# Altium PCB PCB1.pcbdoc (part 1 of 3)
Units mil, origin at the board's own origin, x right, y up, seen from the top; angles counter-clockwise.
Board outline 4706 x 2788 mil, 2 copper layers (Top Layer, Bottom Layer); 153 components, 206 nets, 1095 pads, 513 vias.
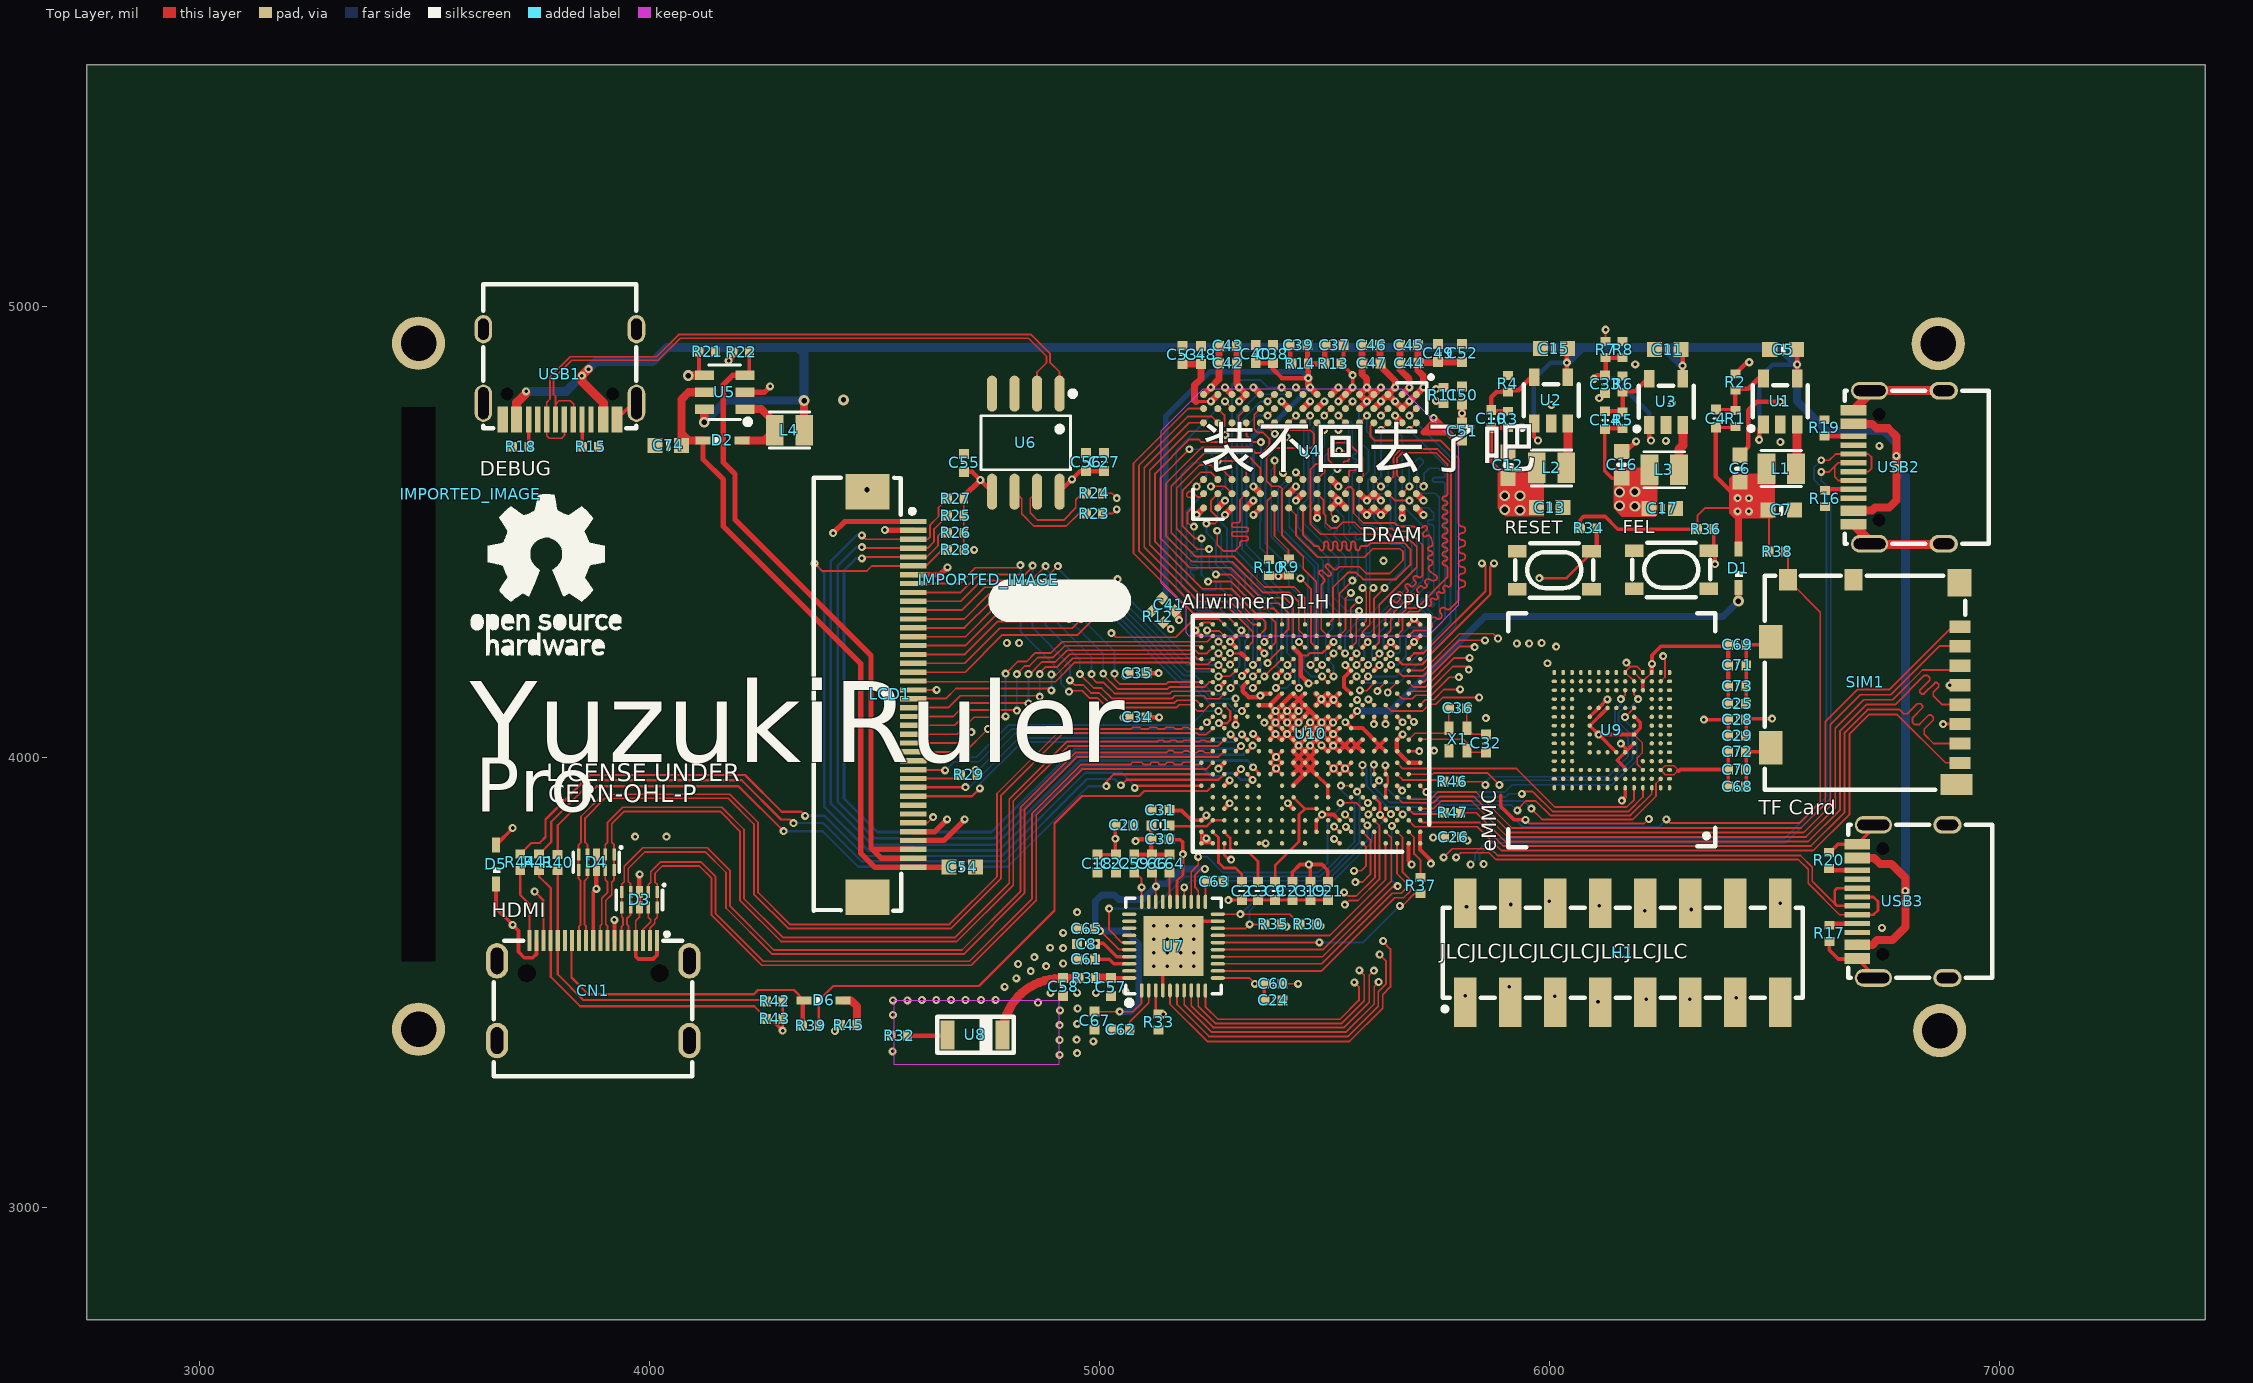
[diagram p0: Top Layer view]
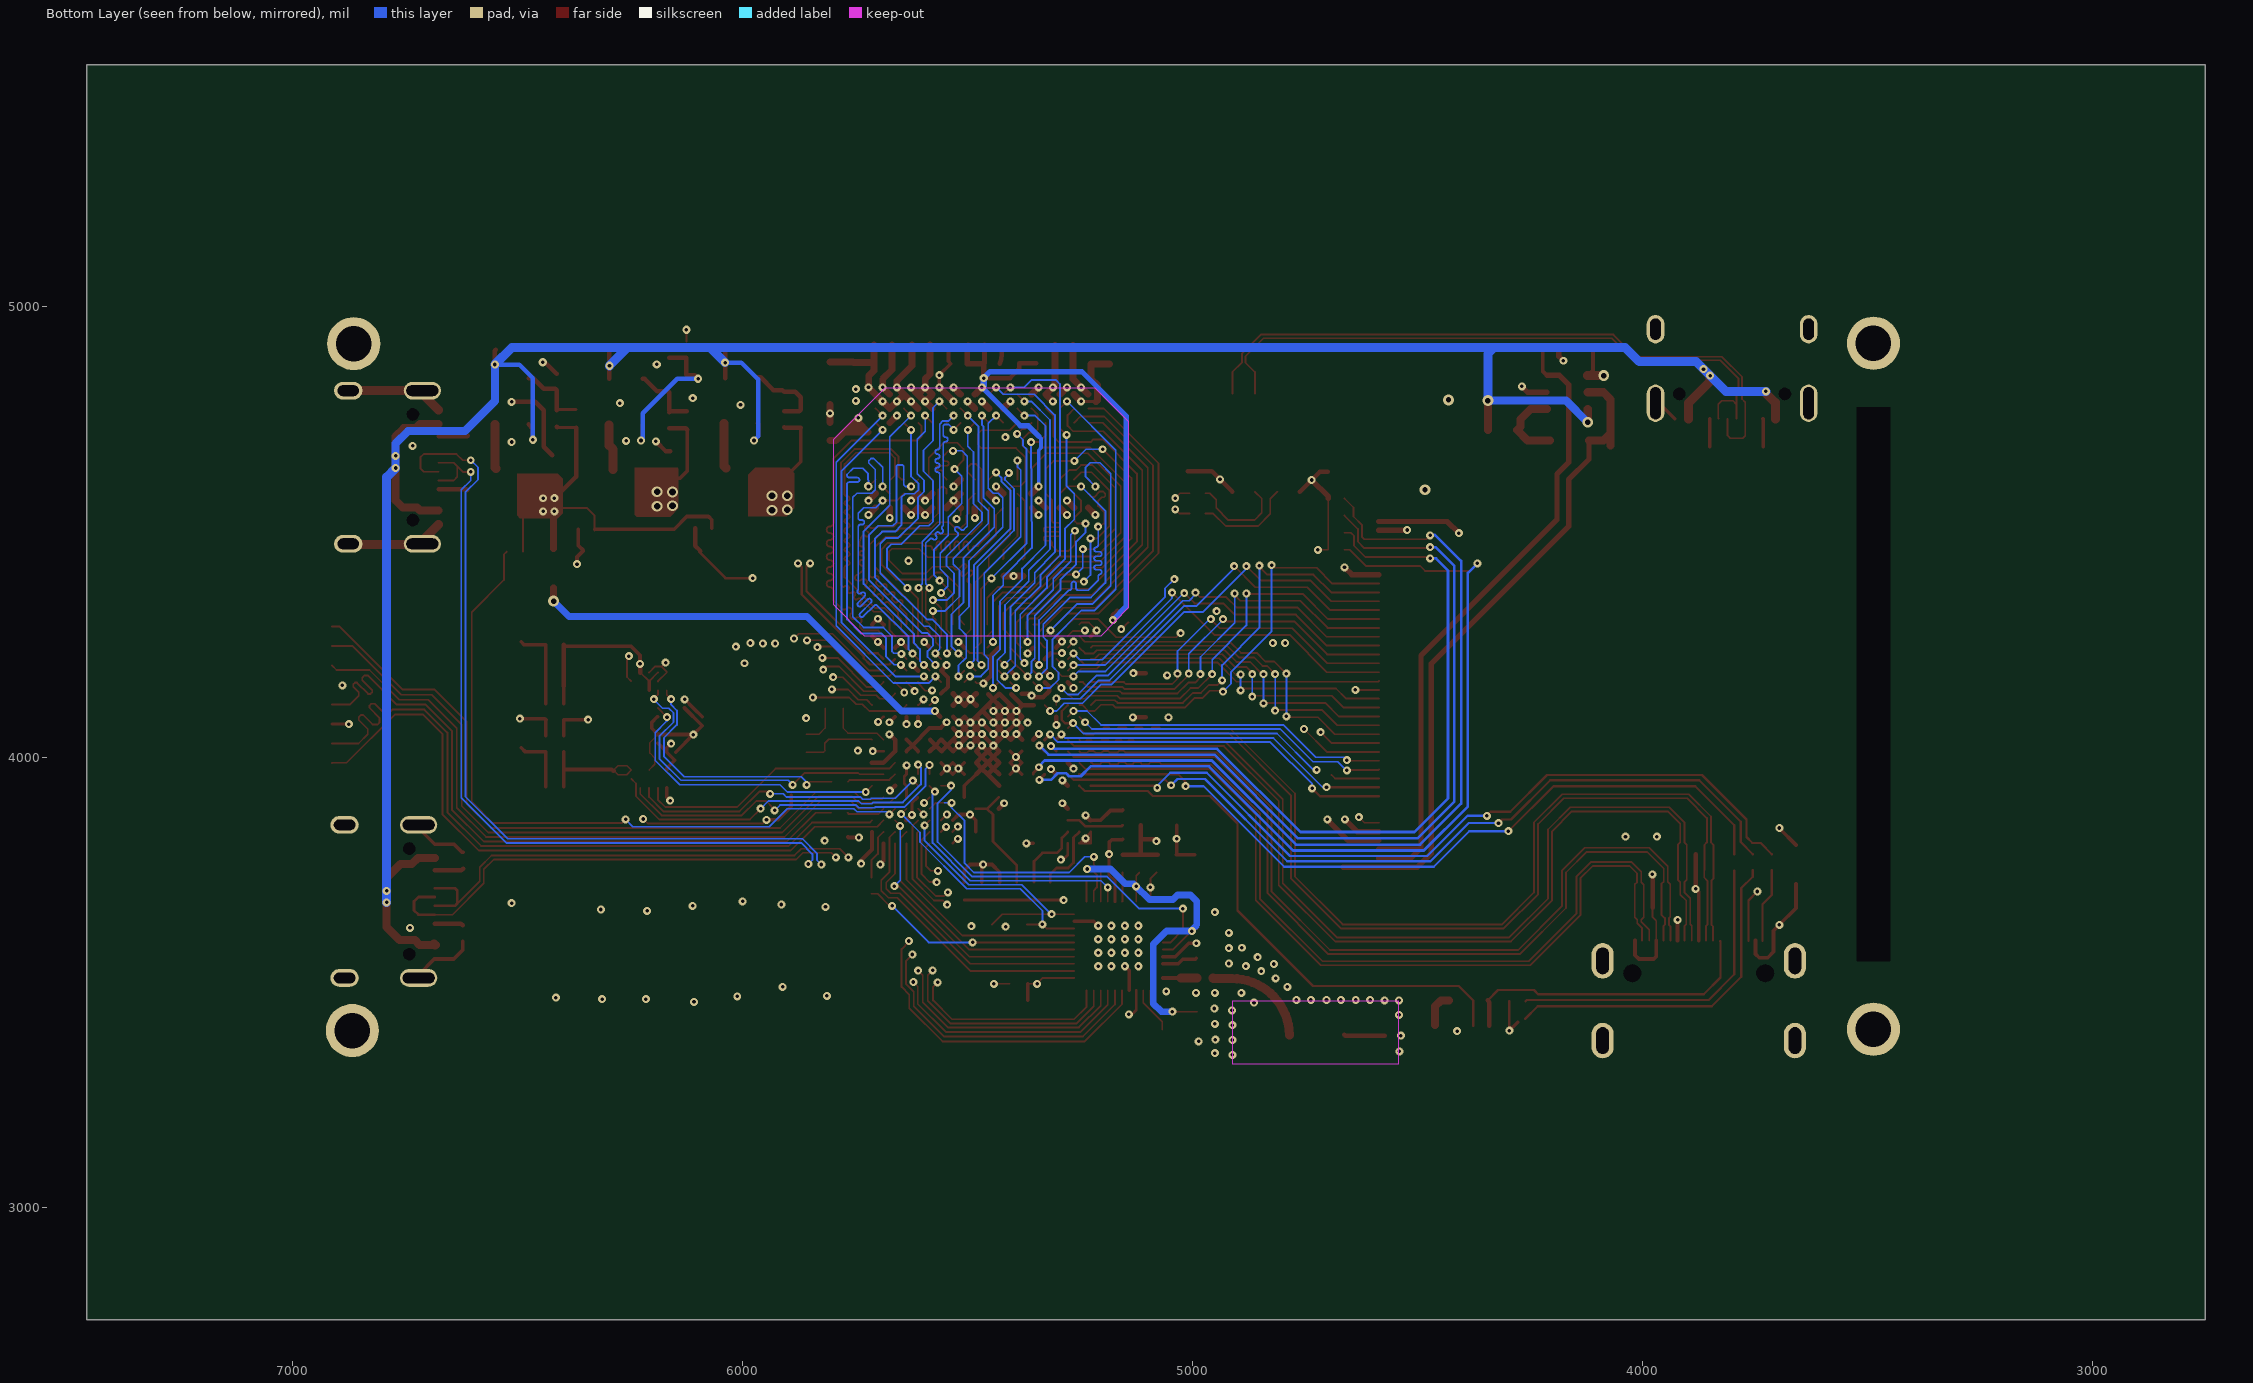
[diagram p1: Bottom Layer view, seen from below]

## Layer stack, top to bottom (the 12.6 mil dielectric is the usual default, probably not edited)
Top Solder: solder mask 0.4, Solder Resist, Dk 3.5
Top Layer: signal copper 1.4
Dielectric 1: dielectric 12.6, FR-4, Dk 4.8
Bottom Layer: signal copper 1.4
Bottom Solder: solder mask 0.4, Solder Resist, Dk 3.5

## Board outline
7456,2750 2750,2750 2750,5538 7456,5538
cut-out: 3450,3546 3524,3546 3524,4777 3450,4777

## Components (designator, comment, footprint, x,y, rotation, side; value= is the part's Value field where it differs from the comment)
C1 "" C0402-NSK 5135,3848.5 r0 top
C2 "" C0402-NSK 5316,3702.5 r90 top
C3 "" C0402-NSK 5352,3702.5 r90 top
C4 "20pf" C0402-NSK_2 6369.14,4752.11 r270 top
C5 "10u" C0603-NSK 6518.14,4905.11 r0 top
C6 "22uf" C0603-NSK 6422.14,4641.11 r270 top
C7 "22uf" C0603-NSK 6514.14,4549.11 r180 top
C8 "" C0402-NSK 4970,3584.5 r0 top
C9 "" C0402-NSK 5390,3702.5 r90 top
C10 "20pf" C0402-NSK_2 5869.87,4751.4 r270 top
C11 "10u" C0603-NSK 6261.87,4905.4 r0 top
C12 "10uf" C0603-NSK 5906.87,4648.4 r270 top
C13 "22uf" C0603-NSK 5999.87,4554.4 r180 top
C14 "20pf" C0402-NSK_2 6122.87,4748.4 r270 top
C15 "10u" C0603-NSK 6009.34,4907.4 r0 top
C16 "10uf" C0603-NSK 6159.87,4649.4 r270 top
C17 "22uf" C0603-NSK 6249.87,4552.4 r180 top
C18 "100nf" C0402-NSK_2 4995,3763.5 r90 top
C19 "100nf" C0402-NSK_2 5468,3702.5 r90 top
C20 "100nf" C0402-NSK_2 5055,3848.5 r180 top
C21 "100nf" C0402-NSK_2 5507,3702.5 r90 top
C22 "100nf" C0402-NSK_2 5036,3763.5 r90 top
C23 "100nf" C0402-NSK_2 5428,3702.5 r90 top
C24 "100nf" C0402-NSK_2 5386,3459.5 r180 top
C25 "100nf" C0402-NSK_2 6416,4118.5 r180 top
C26 "100nf" C0402-NSK_2 5785,3822.5 r180 top
C27 "100nf" C0402-NSK_2 5010,4655.5 r270 top
C28 "100nf" C0402-NSK_2 6415.95,4083.2 r0 top
C29 "100nf" C0402-NSK_2 6416,4047.5 r0 top
C30 "100nf" C0402-NSK_2 5135,3817.5 r0 top
C31 "100nf" C0402-NSK_2 5135,3882.5 r0 top
C32 "" C0402-NSK 5858,4030.5 r90 top
C33 "100n" C0402-NSK_2 6122.87,4828.4 r90 top
C34 "2.2uf" C0402-NSK_2 5084,4088.5 r0 top
C35 "100nf" C0402-NSK_2 5084,4186.5 r0 top
C36 "" C0402-NSK 5796,4108.5 r0 top
C37 "100nf" c0402-nsk 5521.7,4915.46 r0 top
C38 "100nf" C0402-NSK_2 5384.7,4895.46 r270 top
C39 "100nf" C0402-NSK_2 5441.7,4915.46 r0 top
C40 "100nf" C0402-NSK_2 5346.7,4895.46 r270 top
C41 "100nf" C0402-NSK_2 5153.27,4338.92 r315 top
C42 "100nf" C0402-NSK_2 5285,4874.5 r0 top
C43 "100nf" C0402-NSK_2 5285,4913.5 r0 top
C44 "100nf" C0402-NSK_2 5687.99,4875.5 r0 top
C45 "100nf" C0402-NSK_2 5687,4915.5 r0 top
C46 "100nf" C0402-NSK_2 5603,4915.5 r0 top
C47 "100nf" C0402-NSK_2 5604,4874.5 r0 top
C48 "100nf" C0402-NSK_2 5225,4893.5 r270 top
C49 "100nf" C0402-NSK_2 5752,4897.5 r270 top
C50 "100nf" C0402-NSK_2 5805,4803.5 r270 top
C51 "100nf" C0402-NSK_2 5805,4723.5 r90 top
C52 "100nf" C0402-NSK_2 5805,4897.5 r270 top
C53 "100nf" C0402-NSK_2 5184,4893.5 r270 top
C54 "" C0603-NSK 4695,3755.5 r180 top
C55 "" C0402-NSK 4699,4653.5 r90 top
C56 "" C0402-NSK 4970,4655.5 r270 top
C57 "" C0402-NSK 5025.16,3489.2 r90 top
C58 "" C0402-NSK 4919,3489.5 r90 top
C59 "" C0402-NSK 5077,3763.5 r90 top
C60 "" C0402-NSK 5386,3496.5 r0 top
C61 "" C0402-NSK 4970,3550.5 r180 top
C62 "" C0402-NSK 5047,3394.5 r180 top
C63 "" C0402-NSK 5255,3723.5 r0 top
C64 "" C0402-NSK 5155,3763.5 r90 top
C65 "" C0402-NSK 4970,3618.5 r180 top
C66 "" C0402-NSK 5116,3763.5 r90 top
C67 "" C0402-NSK 4989,3414.5 r270 top
C68 "" C0402-NSK 6416,3934.5 r180 top
C69 "" C0402-NSK 6416.36,4249.22 r0 top
C70 "" C0402-NSK 6416,3972.5 r180 top
C71 "" C0402-NSK 6416.36,4203.53 r0 top
C72 "" C0402-NSK 6416,4011.5 r180 top
C73 "" C0402-NSK 6416.36,4157.85 r0 top
C74 "" C0603-NSK 4042,4692.5 r0 top
CN1 "" HDMI-SMD_HD219F-3D05200 3875,3481.5 r0 top
D1 "" SOD-323_L1.8-W1.3-LS2.5-NSK 6419,4419.5 r90 top
D2 "" SOD-323_L1.8-W1.3-LS2.5-NSK 4162,4703.5 r0 top
D3 "" SLP2510P8_L2.5-W1.0-P0.50-BL 3977.7,3682.8 r180 top
D4 "" SLP2510P8_L2.5-W1.0-P0.50-BL 3882,3766.5 r180 top
D5 "" SOD-323_L1.8-W1.3-LS2.5-NSK 3659,3761.5 r90 top
D6 "" SOD-323_L1.8-W1.3-LS2.5-NSK 4387,3459.5 r0 top
FEL "" KEY-SMD_4P-L4.2-W3.2-P2.20-LS4.6 6270,4416.5 r0 top
H1 "" HDR-SMD_16P-P2.54-V-M-R2-C8-S7.4 6162,3565.5 r0 top
IMPORTED_IMAGE "IMPORTED_IMAGE" IMPORTED_IMAGE 3603,4583.5 r0 top
IMPORTED_IMAGE "IMPORTED_IMAGE" IMPORTED_IMAGE 4754,4394.5 r0 top
L1 "" IND-SMD_L2.0-W1.6_1 6514.14,4641.11 r0 top
L2 "" IND-SMD_L2.0-W1.6_1 6003.87,4642.4 r0 top
L3 "" IND-SMD_L2.0-W1.6_1 6254.27,4638.4 r0 top
L4 "" IND-SMD_L2.0-W1.6 4311,4726.5 r0 top
LCD1 "" FPC-SMD_40P-P0.50_FPC-05F-40PH20_R 4535,4139.5 r270 top
R1 "680K" R0402-NSK_2 6412.14,4752.11 r270 top
R2 "150K" R0402-NSK_2 6412.14,4833.11 r270 top
R3 "150K" R0402-NSK_2 5906.87,4750.4 r270 top
R4 "100K" R0402-NSK_2 5906.87,4829.4 r270 top
R5 "75k" R0402-NSK_2 6161.87,4748.4 r270 top
R6 "150K" R0402-NSK_2 6161.87,4828.4 r270 top
R7 "100k" R0402-NSK_2 6123.87,4905.4 r90 top
R8 "100k" R0402-NSK_2 6161.87,4905.4 r270 top
R9 "240" R0402-NSK_1 5420.5,4422.15 r270 top
R10 "240" R0402-NSK_1 5376.5,4421.16 r270 top
R11 "100" R0402-NSK_1 5763.7,4803.46 r90 top
R12 "240" R0402-NSK_1 5129.27,4311.92 r315 top
R13 "2K" R0402-NSK_1 5518.5,4874.15 r0 top
R14 "2K" R0402-NSK_1 5445.5,4874.15 r0 top
R15 "5k1" R0402-NSK_2 3869,4689.5 r180 top
R16 "5k1" R0402-NSK_2 6611,4574.5 r90 top
R17 "5k1" R0402-NSK_2 6621,3608.5 r90 top
R18 "5k1" R0402-NSK_2 3714,4689.5 r180 top
R19 "5k1" R0402-NSK_2 6610,4731.5 r90 top
R20 "5k1" R0402-NSK_2 6620,3770.5 r90 top
R21 "" R0402-NSK 4128,4900.5 r180 top
R22 "" R0402-NSK 4203.99,4899.49 r0 top
R23 "100" R0402-NSK_2 4988.5,4541.01 r180 top
R24 "100" R0402-NSK_2 4988.5,4586.01 r180 top
R25 "" R0402-NSK 4680,4536.51 r0 top
R26 "" R0402-NSK 4680,4498.51 r0 top
R27 "" R0402-NSK 4680,4574.51 r0 top
R28 "" R0402-NSK 4680,4460.51 r0 top
R29 "" R0402-NSK 4709,3960.5 r180 top
R30 "" R0402-NSK 5463,3628.5 r0 top
R31 "" R0402-NSK 4972.16,3509.2 r180 top
R32 "" R0402-NSK 4555,3381.5 r180 top
R33 "" R0402-NSK 5131,3411.5 r270 top
R34 "10k" R0402-NSK_2 6086,4508.5 r180 top
R35 "" R0402-NSK 5386,3628.5 r0 top
R36 "10k" R0402-NSK_2 6346,4506.5 r0 top
R37 "33" R0402-NSK_1 5713,3714.5 r270 top
R38 "" R0402-NSK 6505,4456.5 r0 top
R39 "" R0402-NSK 4358,3403.5 r0 top
R40 "" R0402-NSK 3796,3765.5 r90 top
R41 "" R0402-NSK 3755,3766.5 r90 top
R42 "" R0402-NSK 4278,3457.51 r180 top
R43 "" R0402-NSK 4278,3418.5 r180 top
R44 "" R0402-NSK 3713,3766.5 r90 top
R45 "" R0402-NSK 4443,3404.5 r0 top
R46 "" R0402-NSK 5783,3945.5 r0 top
R47 "" R0402-NSK 5784,3876.5 r0 top
RESET "" KEY-SMD_4P-L4.2-W3.2-P2.20-LS4.6 6010,4415.5 r0 top
SIM1 "" SIM-SMD_8P-1040310811 6701,4166.5 r90 top
U1 "" SOT-23-5_L3.0-W1.7-P0.95-LS2.8-BR 6512.14,4790.11 r270 top
U2 "" SOT-23-5_L3.0-W1.7-P0.95-LS2.8-BR 6002.87,4792.4 r270 top
U3 "" SOT-23-5_L3.0-W1.7-P0.95-LS2.8-BR 6258.27,4789.21 r270 top
U4 "" FBGA96 5462.1,4677.25 r270 top
U5 "" SOT-23-6_L2.9-W1.6-P0.95-LS2.8-BL 4167,4810.5 r90 top
U6 "" SOP-8_L5.0-W4.0-P1.27-LS6.0-BL 4836,4698.5 r180 top
U7 "" QFN-40_L5.0-W5.0-P0.40-BL-EP3.4 5164.16,3580.2 r0 top
U8 "" FILTER-SMD_1206-2P-L3.2-W1.6-L 4723.15,3382.73 r180 top
U9 "" FBGA-153_L13.0-W11.5 6138.02,4060.03 r180 top
U10 "" "ALLWINNER D1" 5457,4054.5 r270 top
USB1 "" usb-c-smd_typec-304-bcp16_1#1 3801,4850.42 r180 top
USB2 "" usb-c-smd_typec-304-bcp16_1#2 6774.84,4643.92 r90 top
USB3 "" usb-c-smd_typec-304-bcp16_1#2 6783,3679.5 r90 top
X1 "24M" OSC-SMD_4P-L2.0-W1.6-BL 5796,4039.5 r90 top

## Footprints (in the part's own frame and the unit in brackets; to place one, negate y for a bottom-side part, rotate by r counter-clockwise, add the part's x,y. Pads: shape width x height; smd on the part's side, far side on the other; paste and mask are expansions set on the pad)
"ALLWINNER D1" [mil]
  round 10 smd: A1(245.98,255.24) A2(245.98,229.65) A3(245.98,204.06) A4(245.98,178.47) A6(245.98,127.29) A8(245.98,76.11) A11(245.98,-0.67) A13(245.98,-51.85) A15(245.98,-103.03) A17(245.98,-154.21) A18(245.98,-179.8) A19(245.98,-205.39) A20(245.98,-230.98) B1(220.39,255.24) B2(220.39,229.65) B3(220.39,204.06) B4(220.39,178.47) B5(220.39,152.88) B6(220.39,127.29) B7(220.39,101.7) B8(220.39,76.11) B9(220.39,50.52) B10(220.39,24.93) B11(220.39,-0.67) B12(220.39,-26.26) B13(220.39,-51.85) B14(220.39,-77.44) B15(220.39,-103.03) B16(220.39,-128.62) B17(220.39,-154.21) B18(220.39,-179.8) B19(220.39,-205.39) B20(220.39,-230.98) C1(194.8,255.24) C2(194.8,229.65) C3(194.8,204.06) C4(194.8,178.47) C5(194.8,152.88) C6(194.8,127.29) C7(194.8,101.7) C8(194.8,76.11) C9(194.8,50.52) C10(194.8,24.93) C11(194.8,-0.67) C12(194.8,-26.26) C13(194.8,-51.85) C14(194.8,-77.44) C15(194.8,-103.03) C16(194.8,-128.62) C17(194.8,-154.21) C18(194.8,-179.8) C19(194.8,-205.39) C20(194.8,-230.98) D1(169.21,255.24) D2(169.21,229.65) D3(169.21,204.06) D4(169.21,178.47) D5(169.21,152.88) D6(169.21,127.29) D7(169.21,101.7) D9(169.21,50.52) D10(169.21,24.93) D12(169.21,-26.26) D13(169.21,-51.85) D15(169.21,-103.03) D16(169.21,-128.62) D17(169.21,-154.21) D18(169.21,-179.8) D19(169.21,-205.39) D20(169.21,-230.98) E2(143.62,229.65) E3(143.62,204.06) E4(143.62,178.47) E5(143.62,152.88) E6(143.62,127.29) E7(143.62,101.7) E9(143.62,50.52) E10(143.62,24.93) E12(143.62,-26.26) E13(143.62,-51.85) E15(143.62,-103.03) E16(143.62,-128.62) E17(143.62,-154.21) E18(143.62,-179.8) E19(143.62,-205.39) F1(118.03,255.24) F2(118.03,229.65) F3(118.03,204.06) F4(118.03,178.47) F5(118.03,152.88) F6(118.03,127.29) F7(118.03,101.7) F9(118.03,50.52) F10(118.03,24.93) F12(118.03,-26.26) F13(118.03,-51.85) F15(118.03,-103.03) F16(118.03,-128.62) F17(118.03,-154.21) F18(118.03,-179.8) F19(118.03,-205.39) F20(118.03,-230.98) G2(92.44,229.65) G3(92.44,204.06) G4(92.44,178.47) G5(92.44,152.88) G6(92.44,127.29) G7(92.44,101.7) G8(92.44,76.11) G9(92.44,50.52) G10(92.44,24.93) G11(92.44,-0.67) G12(92.44,-26.26) G13(92.44,-51.85) G14(92.44,-77.44) G15(92.44,-103.03) G16(92.44,-128.62) G17(92.44,-154.21) G18(92.44,-179.8) G19(92.44,-205.39) H1(66.85,255.24) H2(66.85,229.65) H3(66.85,204.06) H7(66.85,101.7) H8(66.85,76.11) H9(66.85,50.52) H10(66.85,24.93) H11(66.85,-0.67) H12(66.85,-26.26) H13(66.85,-51.85) H14(66.85,-77.44) H18(66.85,-179.8) H19(66.85,-205.39) H20(66.85,-230.98) J2(41.26,229.65) J3(41.26,204.06) J4(41.26,178.47) J5(41.26,152.88) J6(41.26,127.29) J7(41.26,101.7) J8(41.26,76.11) J9(41.26,50.52) J10(41.26,24.93) J11(41.26,-0.67) J12(41.26,-26.26) J13(41.26,-51.85) J14(41.26,-77.44) J15(41.26,-103.03) J16(41.26,-128.62) J17(41.26,-154.21) J18(41.26,-179.8) J19(41.26,-205.39) K1(15.67,255.24) K2(15.67,229.65) K3(15.67,204.06) K4(15.67,178.47) K5(15.67,152.88) K6(15.67,127.29) K7(15.67,101.7) K8(15.67,76.11) K9(15.67,50.52) K10(15.67,24.93) K11(15.67,-0.67) K12(15.67,-26.26) K13(15.67,-51.85) K14(15.67,-77.44) K15(15.67,-103.03) K16(15.67,-128.62) K17(15.67,-154.21) K18(15.67,-179.8) K19(15.67,-205.39) L2(-9.93,229.65) L3(-9.93,204.06) L7(-9.93,101.7) L8(-9.93,76.11) L9(-9.93,50.52) L10(-9.93,24.93) L11(-9.93,-0.67) L12(-9.93,-26.26) L13(-9.93,-51.85) L14(-9.93,-77.44) L18(-9.93,-179.8) L19(-9.93,-205.39) L20(-9.93,-230.98) M2(-35.52,229.65) M3(-35.52,204.06) M4(-35.52,178.47) M5(-35.52,152.88) M6(-35.52,127.29) M7(-35.52,101.7) M8(-35.52,76.11) M9(-35.52,50.52) M10(-35.52,24.93) M11(-35.52,-0.67) M12(-35.52,-26.26) M13(-35.52,-51.85) M14(-35.52,-77.44) M15(-35.52,-103.03) M16(-35.52,-128.62) M17(-35.52,-154.21) M18(-35.52,-179.8) M19(-35.52,-205.39) N1(-61.11,255.24) N2(-61.11,229.65) N3(-61.11,204.06) N4(-61.11,178.47) N5(-61.11,152.88) N6(-61.11,127.29) N7(-61.11,101.7) N8(-61.11,76.11) N9(-61.11,50.52) N10(-61.11,24.93) N11(-61.11,-0.67) N12(-61.11,-26.26) N13(-61.11,-51.85) N14(-61.11,-77.44) N15(-61.11,-103.03) N16(-61.11,-128.62) N17(-61.11,-154.21) N18(-61.11,-179.8) N19(-61.11,-205.39) N20(-61.11,-230.98) P2(-86.7,229.65) P3(-86.7,204.06) P7(-86.7,101.7) P8(-86.7,76.11) P9(-86.7,50.52) P10(-86.7,24.93) P11(-86.7,-0.67) P12(-86.7,-26.26) P13(-86.7,-51.85) P14(-86.7,-77.44) P18(-86.7,-179.8) P19(-86.7,-205.39) R1(-112.29,255.24) R2(-112.29,229.65) R3(-112.29,204.06) R4(-112.29,178.47) R5(-112.29,152.88) R6(-112.29,127.29) R7(-112.29,101.7) R9(-112.29,50.52) R10(-112.29,24.93) R12(-112.29,-26.26) R13(-112.29,-51.85) R15(-112.29,-103.03) R16(-112.29,-128.62) R17(-112.29,-154.21) R18(-112.29,-179.8) R19(-112.29,-205.39) R20(-112.29,-230.98) T2(-137.88,229.65) T3(-137.88,204.06) T4(-137.88,178.47) T5(-137.88,152.88) T6(-137.88,127.29) T7(-137.88,101.7) T9(-137.88,50.52) T10(-137.88,24.93) T12(-137.88,-26.26) T13(-137.88,-51.85) T15(-137.88,-103.03) T16(-137.88,-128.62) T17(-137.88,-154.21) T18(-137.88,-179.8) T19(-137.88,-205.39) U1(-163.47,255.24) U2(-163.47,229.65) U3(-163.47,204.06) U4(-163.47,178.47) U5(-163.47,152.88) U6(-163.47,127.29) U7(-163.47,101.7) U9(-163.47,50.52) U10(-163.47,24.93) U12(-163.47,-26.26) U13(-163.47,-51.85) U15(-163.47,-103.03) U16(-163.47,-128.62) U17(-163.47,-154.21) U18(-163.47,-179.8) U19(-163.47,-205.39) U20(-163.47,-230.98) V1(-189.06,255.24) V2(-189.06,229.65) V3(-189.06,204.06) V4(-189.06,178.47) V5(-189.06,152.88) V6(-189.06,127.29) V7(-189.06,101.7) V8(-189.06,76.11) V9(-189.06,50.52) V10(-189.06,24.93) V11(-189.06,-0.67) V12(-189.06,-26.26) V13(-189.06,-51.85) V14(-189.06,-77.44) V15(-189.06,-103.03) V16(-189.06,-128.62) V17(-189.06,-154.21) V18(-189.06,-179.8) V19(-189.06,-205.39) V20(-189.06,-230.98) W1(-214.65,255.24) W2(-214.65,229.65) W3(-214.65,204.06) W4(-214.65,178.47) W5(-214.65,152.88) W6(-214.65,127.29) W7(-214.65,101.7) W8(-214.65,76.11) W9(-214.65,50.52) W10(-214.65,24.93) W11(-214.65,-0.67) W12(-214.65,-26.26) W13(-214.65,-51.85) W14(-214.65,-77.44) W15(-214.65,-103.03) W16(-214.65,-128.62) W17(-214.65,-154.21) W18(-214.65,-179.8) W19(-214.65,-205.39) W20(-214.65,-230.98) Y1(-240.24,255.24) Y2(-240.24,229.65) Y3(-240.24,204.06) Y4(-240.24,178.47) Y6(-240.24,127.29) Y8(-240.24,76.11) Y9(-240.24,50.52) Y11(-240.24,-0.67) Y13(-240.24,-51.85) Y15(-240.24,-103.03) Y17(-240.24,-154.21) Y18(-240.24,-179.8) Y19(-240.24,-205.39) Y20(-240.24,-230.98)
  silkscreen extent -260,-250 265,275
C0402-NSK [mil]
  rect 22x22 smd: 1(-19.99,0) 2(20.01,0)
  silkscreen extent 0,-5 0,6
c0402-nsk [mil]
  rect 22x22 smd: 1(-20,0) 2(20,0)
  silkscreen extent 0,-5 0,6
C0402-NSK_2 [mil]
  rect 22x22 smd: 1(-19.99,0) 2(20.01,0)
  silkscreen extent 0,-5 0,6
C0603-NSK [mm]
  rect 0.85x0.85 smd: 1(-0.75,0) 2(0.75,0)
  silkscreen extent 0,-0.21 0,0.21
FBGA96 [mil]
  round 15.7 smd: A1(-128.4,241.4) A2(-96.9,241.4) A3(-65.4,241.4) A7(60.6,241.4) A8(92.1,241.4) A9(123.6,241.4) B1(-128.4,209.9) B2(-96.9,209.9) B3(-65.4,209.9) B7(60.6,209.9) B8(92.1,209.9) B9(123.6,209.9) C1(-128.4,178.4) C2(-96.9,178.4) C3(-65.4,178.4) C7(60.6,178.4) C8(92.1,178.4) C9(123.6,178.4) D1(-128.4,146.9) D2(-96.9,146.9) D3(-65.4,146.9) D7(60.6,146.9) D8(92.1,146.9) D9(123.6,146.9) E1(-128.4,115.4) E2(-96.9,115.4) E3(-65.4,115.4) E7(60.6,115.4) E8(92.1,115.4) E9(123.6,115.4) F1(-128.4,83.9) F2(-96.9,83.9) F3(-65.4,83.9) F7(60.6,83.9) F8(92.1,83.9) F9(123.6,83.9) G1(-128.4,52.4) G2(-96.9,52.4) G3(-65.4,52.4) G7(60.6,52.4) G8(92.1,52.4) G9(123.6,52.4) H1(-128.4,20.9) H2(-96.9,20.9) H3(-65.4,20.9) H7(60.6,20.9) H8(92.1,20.9) H9(123.6,20.9) J1(-128.4,-10.6) J2(-96.9,-10.6) J3(-65.4,-10.6) J7(60.6,-10.6) J8(92.1,-10.6) J9(123.6,-10.6) K1(-128.4,-42.1) K2(-96.9,-42.1) K3(-65.4,-42.1) K7(60.6,-42.1) K8(92.1,-42.1) K9(123.6,-42.1) L1(-128.4,-73.6) L2(-96.9,-73.6) L3(-65.4,-73.6) L7(60.6,-73.6) L8(92.1,-73.6) L9(123.6,-73.6) M1(-128.4,-105.1) M2(-96.9,-105.1) M3(-65.4,-105.1) M7(60.6,-105.1) M8(92.1,-105.1) M9(123.6,-105.1) N1(-128.4,-136.6) N2(-96.9,-136.6) N3(-65.4,-136.6) N7(60.6,-136.6) N8(92.1,-136.6) N9(123.6,-136.6) P1(-128.4,-168.1) P2(-96.9,-168.1) P3(-65.4,-168.1) P7(60.6,-168.1) P8(92.1,-168.1) P9(123.6,-168.1) R1(-128.4,-199.6) R2(-96.9,-199.6) R3(-65.4,-199.6) R7(60.6,-199.6) R8(92.1,-199.6) R9(123.6,-199.6) T1(-128.4,-231.1) T2(-96.9,-231.1) T3(-65.4,-231.1) T7(60.6,-231.1) T8(92.1,-231.1) T9(123.6,-231.1)
  silkscreen extent -168,-255 149,275
FBGA-153_L13.0-W11.5 [mm]
  oval 0.2x0.305 smd: A1(-3.25,3.25) A2(-2.75,3.25) A3(-2.25,3.25) A4(-1.75,3.25) A5(-1.25,3.25) A6(-0.75,3.25) A7(-0.25,3.25) A8(0.25,3.25) A9(0.75,3.25) A10(1.25,3.25) A11(1.75,3.25) A12(2.25,3.25) A13(2.75,3.25) A14(3.25,3.25) P1(-3.25,-3.25) P2(-2.75,-3.25) P3(-2.25,-3.25) P4(-1.75,-3.25) P5(-1.25,-3.25) P6(-0.75,-3.25) P7(-0.25,-3.25) P8(0.25,-3.25) P9(0.75,-3.25) P10(1.25,-3.25) P11(1.75,-3.25) P12(2.25,-3.25) P13(2.75,-3.25) P14(3.25,-3.25)
  oval 0.305x0.2 smd: B1(-3.25,2.75) B14(3.25,2.75) C1(-3.25,2.25) C14(3.25,2.25) D1(-3.25,1.75) D14(3.25,1.75) E1(-3.25,1.25) E14(3.25,1.25) F1(-3.25,0.75) F14(3.25,0.75) G1(-3.25,0.25) G14(3.25,0.25) H1(-3.25,-0.25) H14(3.25,-0.25) J1(-3.25,-0.75) J14(3.25,-0.75) K1(-3.25,-1.25) K14(3.25,-1.25) L1(-3.25,-1.75) L14(3.25,-1.75) M1(-3.25,-2.25) M14(3.25,-2.25) N1(-3.25,-2.75) N14(3.25,-2.75)
  round 0.25 smd: B2(-2.75,2.75) B3(-2.25,2.75) B4(-1.75,2.75) B5(-1.25,2.75) B6(-0.75,2.75) B7(-0.25,2.75) B8(0.25,2.75) B9(0.75,2.75) B10(1.25,2.75) B11(1.75,2.75) B12(2.25,2.75) B13(2.75,2.75) C2(-2.75,2.25) C3(-2.25,2.25) C4(-1.75,2.25) C5(-1.25,2.25) C6(-0.75,2.25) C7(-0.25,2.25) C8(0.25,2.25) C9(0.75,2.25) C10(1.25,2.25) C11(1.75,2.25) C12(2.25,2.25) C13(2.75,2.25) D2(-2.75,1.75) D3(-2.25,1.75) D4(-1.75,1.75) D12(2.25,1.75) D13(2.75,1.75) E2(-2.75,1.25) E3(-2.25,1.25) E5(-1.25,1.25) E6(-0.75,1.25) E7(-0.25,1.25) E8(0.25,1.25) E9(0.75,1.25) E10(1.25,1.25) E12(2.25,1.25) E13(2.75,1.25) F2(-2.75,0.75) F3(-2.25,0.75) F5(-1.25,0.75) F10(1.25,0.75) F12(2.25,0.75) F13(2.75,0.75) G2(-2.75,0.25) G3(-2.25,0.25) G5(-1.25,0.25) G10(1.25,0.25) G12(2.25,0.25) G13(2.75,0.25) H2(-2.75,-0.25) H3(-2.25,-0.25) H5(-1.25,-0.25) H10(1.25,-0.25) H12(2.25,-0.25) H13(2.75,-0.25) J2(-2.75,-0.75) J3(-2.25,-0.75) J5(-1.25,-0.75) J10(1.25,-0.75) J12(2.25,-0.75) J13(2.75,-0.75) K2(-2.75,-1.25) K3(-2.25,-1.25) K5(-1.25,-1.25) K6(-0.75,-1.25) K7(-0.25,-1.25) K8(0.25,-1.25) K9(0.75,-1.25) K10(1.25,-1.25) K12(2.25,-1.25) K13(2.75,-1.25) L2(-2.75,-1.75) L3(-2.25,-1.75) L12(2.25,-1.75) L13(2.75,-1.75) M2(-2.75,-2.25) M3(-2.25,-2.25) M4(-1.75,-2.25) M5(-1.25,-2.25) M6(-0.75,-2.25) M7(-0.25,-2.25) M8(0.25,-2.25) M9(0.75,-2.25) M10(1.25,-2.25) M11(1.75,-2.25) M12(2.25,-2.25) M13(2.75,-2.25) N2(-2.75,-2.75) N3(-2.25,-2.75) N4(-1.75,-2.75) N5(-1.25,-2.75) N6(-0.75,-2.75) N7(-0.25,-2.75) N8(0.25,-2.75) N9(0.75,-2.75) N10(1.25,-2.75) N11(1.75,-2.75) N12(2.25,-2.75) N13(2.75,-2.75)
  silkscreen extent -5.84,-6.61 5.84,6.6
FILTER-SMD_1206-2P-L3.2-W1.6-L [mil]
  rect 31.5x65.4 smd: 1(-61,0) 2(61,0)
  silkscreen extent -86,-40 84,40
FPC-SMD_40P-P0.50_FPC-05F-40PH20_R [mil]
  rect 11.8x59.1 smd: 1(383.9,50.7) 2(364.2,50.7) 3(344.5,50.7) 4(324.8,50.7) 5(305.1,50.7) 6(285.4,50.7) 7(265.7,50.7) 8(246.1,50.7) 9(226.4,50.7) 10(206.7,50.7) 11(187,50.7) 12(167.3,50.7) 13(147.6,50.7) 14(127.9,50.7) 15(108.3,50.7) 16(88.6,50.7) 17(68.9,50.7) 18(49.2,50.7) 19(29.5,50.7) 20(9.8,50.7) 21(-9.8,50.7) 22(-29.5,50.7) 23(-49.2,50.7) 24(-68.9,50.7) 25(-88.6,50.7) 26(-108.3,50.7) 27(-128,50.7) 28(-147.6,50.7) 29(-167.3,50.7) 30(-187,50.7) 31(-206.7,50.7) 32(-226.4,50.7) 33(-246.1,50.7) 34(-265.8,50.7) 35(-285.4,50.7) 36(-305.1,50.7) 37(-324.8,50.7) 38(-344.5,50.7) 39(-364.2,50.7) 40(-383.9,50.7)
  rect 78.7x98.4 smd: 41(450.4,-50.7) 42(-450.4,-50.7)
  silkscreen extent -481,-171 481,54
HDMI-SMD_HD219F-3D05200 [mil]
  rect 9.1x47.2 smd: 1(141.7,111.2) 2(126,111.2) 3(110.2,111.2) 4(94.5,111.2) 5(78.7,111.2) 6(63,111.2) 7(47.2,111.2) 8(31.5,111.2) 9(15.8,111.2) 10(0,111.2) 11(-15.7,111.2) 12(-31.5,111.2) 13(-47.2,111.2) 14(-63,111.2) 15(-78.7,111.2) 16(-94.5,111.2) 17(-110.2,111.2) 18(-126,111.2) 19(-141.7,111.2)
  oval 49.2x78.7 hole 27.6 slot 59.1 at 90 deg: 20(213.6,-111.2) 21(-213.6,-111.2) 22(213.6,65.9) 23(-213.6,65.9)
  Multi-Layer board cut-out: -127.9,38.4 -129.85,46.95 -135.32,53.8 -143.22,57.61 -151.98,57.61 -159.88,53.8 -165.35,46.95 -167.3,38.4 -167.3,38.4 -165.35,29.85 -159.88,23 -151.98,19.19 -143.22,19.19 -135.32,23 -129.85,29.85 -127.9,38.4
  Multi-Layer board cut-out: 167.3,38.4 165.35,46.95 159.88,53.8 151.98,57.61 143.22,57.61 135.32,53.8 129.85,46.95 127.9,38.4 127.9,38.4 129.85,29.85 135.32,23 143.22,19.19 151.98,19.19 159.88,23 165.35,29.85 167.3,38.4
  silkscreen extent -220,-190 220,129
HDR-SMD_16P-P2.54-V-M-R2-C8-S7.4 [mm]
  rect 1.27x2.8 smd: 1(-8.89,-2.8) 2(-8.89,2.8) 3(-6.35,-2.8) 4(-6.35,2.8) 5(-3.81,-2.8) 6(-3.81,2.8) 7(-1.27,-2.8) 8(-1.27,2.8) 9(1.27,-2.8) 10(1.27,2.8) 11(3.81,-2.8) 12(3.81,2.8) 13(6.35,-2.8) 14(6.35,2.8) 15(8.89,-2.8) 16(8.89,2.8)
  silkscreen extent -10.16,-3.3 10.16,2.53
IMPORTED_IMAGE [mil]
  silkscreen extent 0,-358 335,0
IND-SMD_L2.0-W1.6 [mm]
  rect 1x1.72 smd: 1(0.828,0) 2(-0.828,0)
  silkscreen extent -1.14,-1.02 1.14,1.02
IND-SMD_L2.0-W1.6_1 [mm]
  rect 1x1.72 smd: 1(0.828,0) 2(-0.828,0)
  silkscreen extent -1.14,-1.02 1.14,1.02
KEY-SMD_4P-L4.2-W3.2-P2.20-LS4.6 [mil]
  rect 41.3x27.6 smd: 1(-82.7,42.3) 2(82.7,42.3) 3(-82.7,-42.3) 4(82.7,-42.3)
  silkscreen extent -87,-61 87,60
OSC-SMD_4P-L2.0-W1.6-BL [mil]
  rect 30x20 smd: 1(-25,-20) 2(25,-20) 3(25,20) 4(-25,20)
QFN-40_L5.0-W5.0-P0.40-BL-EP3.4 [mm]
  oval 0.2x0.8 smd: 1(-1.8,-2.499) 2(-1.4,-2.499) 3(-1,-2.499) 4(-0.6,-2.499) 5(-0.2,-2.499) 6(0.2,-2.499) 7(0.6,-2.499) 8(1,-2.499) 9(1.4,-2.499) 10(1.8,-2.499) 21(1.8,2.499) 22(1.4,2.499) 23(1,2.499) 24(0.6,2.499) 25(0.2,2.499) 26(-0.2,2.499) 27(-0.6,2.499) 28(-1,2.499) 29(-1.4,2.499) 30(-1.8,2.499)
  oval 0.8x0.2 smd: 11(2.499,-1.8) 12(2.499,-1.4) 13(2.499,-1) 14(2.499,-0.6) 15(2.499,-0.2) 16(2.499,0.2) 17(2.499,0.6) 18(2.499,1) 19(2.499,1.4) 20(2.499,1.8) 31(-2.499,1.8) 32(-2.499,1.4) 33(-2.499,1) 34(-2.499,0.6) 35(-2.499,0.2) 36(-2.499,-0.2) 37(-2.499,-0.6) 38(-2.499,-1) 39(-2.499,-1.4) 40(-2.499,-1.8)
  rect 3.4x3.4 smd: 41(0,0)
  silkscreen extent -2.7,-3.35 2.7,2.7
R0402-NSK [mil]
  rect 19.68x22 smd: 1(-18,0) 2(18,0)
R0402-NSK_1 [mil]
  rect 19.68x22 smd: 1(-18,0) 2(18,0)
R0402-NSK_2 [mil]
  rect 19.68x22 smd: 1(-18,0) 2(18,0)
SIM-SMD_8P-1040310811 [mil]
  rect 27.6x47.2 smd: 1(123.5,-210.1) 2(80.2,-210.1) 3(36.9,-210.1) 4(-6.4,-210.1) 5(-49.7,-210.1) 6(-93,-210.1) 7(-136.3,-210.1) 8(-179.6,-210.1)
  rect 46.1x70.9 smd: 9(-227.3,-202.3)
  rect 61x53.2 smd: 10(220.4,-209.2)
  rect 47.2x39.4 smd: 11(227.3,26.1) 12(227.3,171.8)
  rect 74.8x53.2 smd: 13(89.5,210.1) 14(-145.6,210.1)
  silkscreen extent -239,-222 236,223
SLP2510P8_L2.5-W1.0-P0.50-BL [mil]
  rect 7.9x26.8 smd: 1(-39.4,-17.3) 2(-19.7,-17.3) 4(19.7,-17.3) 5(39.4,-17.3) 6(39.4,17.3) 7(19.7,17.3) 9(-19.7,17.3) 10(-39.4,17.3)
  rect 15.7x26.8 smd: 3(0,-17.3) 8(0,17.3)
  silkscreen extent -57,-35 51,22
SOD-323_L1.8-W1.3-LS2.5-NSK [mil]
  rect 33.3x17.9 smd: 1(-43.2,0) 2(43.2,0)
  silkscreen extent -18,-10 -6,7
SOP-8_L5.0-W4.0-P1.27-LS6.0-BL [mil]
  oval 22.6x80.14 smd: 1(-75,-108.97) 2(-25,-108.97) 3(25,-108.97) 4(75,-108.97) 5(75,108.97) 6(25,108.97) 7(-25,108.97) 8(-75,108.97)
  silkscreen extent -110,-115 99,60
SOT-23-5_L3.0-W1.7-P0.95-LS2.8-BR [mm]
  rect 1x0.6 smd: 1(1.3,-0.95) 2(1.3,0) 3(1.3,0.95) 4(-1.3,0.95) 5(-1.3,-0.95)
  silkscreen extent -0.9,-1.78 1.65,1.55
SOT-23-6_L2.9-W1.6-P0.95-LS2.8-BL [mil]
  rect 20.95x42.2 smd: 1(-37.4,-45.24) 2(0,-45.24) 3(37.4,-45.24) 4(37.4,45.24) 5(0,45.24) 6(-37.4,45.24)
  silkscreen extent -72,-57 61,35
usb-c-smd_typec-304-bcp16_1#1 [mm]
  oval 1x2.1 hole 0.6 slot 1.8 at 90 deg: 13(-4.32,1.632) 14(4.32,1.632)
  oval 1x1.6 hole 0.6 slot 1.2 at 90 deg: 15(-4.32,-2.548) 16(4.32,-2.548)
  rect 0.6x1.45 smd: A1B12(-3.225,2.547) A4B9(-2.45,2.547) B1A12(3.22,2.547) B4A9(2.45,2.547)
  rect 0.3x1.45 smd: A5(-1.25,2.547) A6(-0.25,2.547) A7(0.25,2.547) A8(1.25,2.547) B5(1.75,2.547) B6(0.75,2.547) B7(-0.75,2.547) B8(-1.75,2.547)
  Multi-Layer board cut-out: 2.63,1.102 2.665,0.95 2.762,0.829 2.902,0.761 3.058,0.761 3.198,0.829 3.296,0.95 3.33,1.102 3.33,1.102 3.296,1.254 3.198,1.376 3.058,1.444 2.902,1.444 2.762,1.376 2.665,1.254 2.63,1.102
  Multi-Layer board cut-out: -3.33,1.102 -3.295,0.95 -3.198,0.829 -3.058,0.761 -2.902,0.761 -2.762,0.829 -2.665,0.95 -2.63,1.102 -2.63,1.102 -2.665,1.254 -2.762,1.376 -2.902,1.444 -3.058,1.444 -3.198,1.376 -3.295,1.254 -3.33,1.102
  silkscreen extent -4.32,-5.08 4.32,3.05
usb-c-smd_typec-304-bcp16_1#2 [mm]
  oval 1x2.1 hole 0.6 slot 1.8 at 90 deg: 13(-4.32,1.632) 14(4.32,1.632)
  oval 1x1.6 hole 0.6 slot 1.2 at 90 deg: 15(-4.32,-2.548) 16(4.32,-2.548)
  rect 0.6x1.45 smd: A1B12(-3.225,2.547) A4B9(-2.45,2.547) B1A12(3.22,2.547) B4A9(2.45,2.547)
  rect 0.3x1.45 smd: A5(-1.25,2.547) A6(-0.25,2.547) A7(0.25,2.547) A8(1.25,2.547) B5(1.75,2.547) B6(0.75,2.547) B7(-0.75,2.547) B8(-1.75,2.547)
  Multi-Layer board cut-out: 2.98,0.752 3.132,0.787 3.254,0.884 3.321,1.024 3.321,1.18 3.254,1.321 3.132,1.418 2.98,1.452 2.98,1.452 2.828,1.418 2.707,1.321 2.639,1.18 2.639,1.024 2.707,0.884 2.828,0.787 2.98,0.752
  Multi-Layer board cut-out: -2.98,0.752 -2.828,0.787 -2.706,0.884 -2.639,1.024 -2.639,1.18 -2.706,1.321 -2.828,1.418 -2.98,1.452 -2.98,1.452 -3.132,1.418 -3.254,1.321 -3.321,1.18 -3.321,1.024 -3.254,0.884 -3.132,0.787 -2.98,0.752
  silkscreen extent -4.32,-5.08 4.32,3.05

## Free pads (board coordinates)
  round 118.11 hole 78.74: 1(3487,3395.5) 1(3487,4919.5) 1(6863,4918.5) 1(6866,3392.5)

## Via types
v1: diameter 17.7, hole 7.9, Top Layer to Bottom Layer, 233 vias
v2: diameter 17.72, hole 7.87, Top Layer to Bottom Layer, 140 vias
v3: diameter 17.7, hole 8, Top Layer to Bottom Layer, 88 vias
v4: diameter 18, hole 8, Top Layer to Bottom Layer, 38 vias
v5: diameter 24, hole 15, Top Layer to Bottom Layer, 8 vias
v6: diameter 24, hole 12, Top Layer to Bottom Layer, 6 vias

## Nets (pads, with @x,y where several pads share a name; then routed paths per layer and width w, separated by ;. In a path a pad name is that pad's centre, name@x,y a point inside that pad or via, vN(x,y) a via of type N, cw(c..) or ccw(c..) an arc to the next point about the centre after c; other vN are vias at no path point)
0V9: C14.2 C16.2 C17.2 C18.2 C19.2 C20.2 C21.2 C22.2 C23.2 L3.2 R5.2 U10.G7 U10.G8 U10.G9 U10.G13 U10.G14 U10.H7 U10.H8 U10.H9 U10.H13 U10.H14 U10.J13 U10.J14 | length 1622.9
  Top Layer w8: C18.2@4995,3783.51 C22.2@5036,3783.51 5034.99,3784.51 v1(5034.99,3818.7) C20.2@5034.99,3848.5 ; U10.G14@5379.06,3961.91 v1(5391.86,3974.71) ; U10.J14@5379.06,4013.09 v1(5391.86,4000.3) ; U10.G13@5404.65,3961.91 v1(5391.86,3974.71) ; U10.J13@5404.65,4013.09 v1(5391.86,4000.3) ; C23.2@5428,3722.51 5428,3744.5 5445,3761.5 v1(5465,3761.5) ; C19.2@5468,3722.51 5468,3758.5 v1(5465,3761.5) ; C21.2@5507,3722.51 5507,3748.5 5494,3761.5 v1(5465,3761.5) ; U10.G9@5507.02,3961.91 v1(5519.82,3974.71) ; U10.H9@5507.02,3987.5 v1(5519.82,3974.71) ; U10.G7@5558.2,3961.91 v1(5545.41,3974.71) ; U10.H7@5558.2,3987.5 v1(5545.41,3974.71) ; C14.2@6121.87,4727.4 6121.87,4635.4 6137.4,4619.87 C16.2@6159.87,4619.87 ; v1(5391.86,3974.71) 5379.06,3987.5 v1(5391.86,4000.3) ; v1(5391.86,3974.71) 5404.65,3987.5 v1(5391.86,4000.3) ; v1(5519.82,3974.71) 5532.61,3987.5 v1(5545.41,3974.71) ; v1(5519.82,3974.71) 5532.61,3961.91 v1(5545.41,3974.71)
  Top Layer w10: C14.2@6121.87,4727.4 6124.87,4730.4 R5.2@6161.87,4730.4
  Mid-Layer 2 w20: v1(5034.99,3818.7) 5064.42,3848.13 5441,3848.13 ; v1(5465,3761.5) 5441,3785.5 5441,3848.13 ; v1(5545.41,3974.71) v1(5519.82,3974.71) 5472.32,3974.71 ; 5417.45,3974.71 v1(5391.86,4000.3) v1(5391.86,3974.71) 5417.45,3974.71 ; 5417.45,3974.71 5472.32,3974.71 ; 5441,3848.13 5441,3875.5 5472.32,3906.82 5472.32,3974.71
  other v5: 6154.87,4558.4 6189,4557.5 6154.87,4588.97 6189,4589.5
1V5: C10.2 C12.2 C13.2 C37.2 C42.2 C43.2 C44.2 C45.2 C46.2 C47.2 C48.2 C49.2 C50.2 C51.2 C52.2 C53.2 L2.2 R3.2 R13.2 U4.A1 U4.A8 U4.B2 U4.C1 U4.C9 U4.D2 U4.D9 U4.E9 U4.F1 U4.G7 U4.H2 U4.H9 U4.K2 U4.K8 U4.N1 U4.N9 U4.R1 U4.R9 U10.N8 U10.N9 U10.N10 U10.P8 U10.P9 U10.P10 | length 1580.7
  Top Layer w6: 5214,4789.5 5214.62,4790.12 v2(5247.04,4790.12)
  Top Layer w8: C42.2@5305,4877.51 C42.2@5306,4876.5 ; C37.2@5541.7,4915.46 5541.7,4879.36 R13.2@5536.5,4874.15 v1(5561.99,4848.66) v2(5561.99,4821.61) ; C10.2@5869.87,4731.39 5869.87,4655.87 C12.2@5906.87,4618.87
  Top Layer w10: C10.2@5869.87,4731.39 5905.87,4731.4 R3.2@5906.87,4732.4
  Top Layer w12: U10.N10@5480.43,4115.26 v4@5493.23,4128.06 ; U10.P10@5480.43,4140.85 v4@5493.23,4128.06 ; v4(5492.7,4128.46) v4@5493.23,4128.06 ; v4@5518.82,4128.06 5506.02,4115.26 v4@5493.23,4128.06 ; U10.N8@5531.61,4115.26 v4(5519.7,4127.46) ; U10.P8@5531.61,4140.85 v4(5519.7,4127.46) ; v4@5493.23,4128.06 5506.02,4140.85 v4(5519.7,4127.46)
  Top Layer w15: C53.2@5184,4873.49 C48.2@5225,4873.49 5225,4840.5 5211,4826.5 5211,4792.5 5214,4789.5 ; v2(5247.04,4790.12) U4.R1@5262.78,4805.86 ; U4.R9@5262.78,4553.9 v2(5278.53,4569.65) ; C43.2@5305,4914.5 5305,4877.51 5305,4826.64 v2(5310.03,4821.61) 5325.77,4805.86 v2(5310.03,4790.12) ; U4.N9@5325.77,4553.9 v2(5341.52,4569.65) ; v2(5404.52,4790.12) U4.K2@5420.26,4774.37 ; U4.K8@5420.26,4585.39 v2(5436.01,4601.14) ; v2(5483.25,4531.63) U4.H9@5483.25,4553.9 ; U4.H2@5483.25,4774.37 v2(5499,4790.12) ; U4.G7@5514.74,4616.89 v2(5530.49,4601.15) ; v2(5530.5,4790.12) 5546.02,4805.64 v2(5561.99,4821.61) ; U4.E9@5577.74,4553.9 v2(5593.49,4538.16) 5609.23,4553.9 v2(5624.98,4538.16) U4.C9@5640.73,4553.9 ; U4.D2@5609.23,4774.37 v2(5624.98,4790.12) ; C46.2@5623,4915.5 5623,4869.49 5656.48,4836.02 v2(5656.48,4821.61) U4.C1@5640.74,4805.86 ; v2(5624.98,4790.12) U4.C1@5640.73,4805.86 ; v2(5687.97,4790.12) 5672.22,4774.37 v2(5656.48,4790.12) U4.C1@5640.74,4805.86 ; v2(5687.97,4790.12) 5703.52,4805.64 v2(5719.47,4821.61) 5719,4822.09 5719,4846.5 5707,4858.49 C44.2@5707,4876.5 ; U4.A8@5703.72,4585.39 v2(5719.47,4569.65) ; C45.2@5707,4915.5 C44.2@5707,4876.5 ; C51.2@5805,4743.51 v1(5805,4763.5) C50.2@5805,4783.49 ; C52.2@5805,4877.49 5754,4877.49 5753,4876.5 C44.2@5707,4876.5
  other v5: 5934,4548.5 5900,4549.5 5900,4580.5 5934,4580.5
3V3: C4.2 C6.2 C7.2 C8.2 C24.2 C25.2 C26.2 C27.2 C28.2 C29.2 C30.2 C31.2 C55.1 C56.2 C59.1 C60.1 C69.1 C71.1 C73.1 D1.2 H1.16 L1.2 LCD1.5 LCD1.39 R1.2 R7.2 R25.2 R26.2 R27.2 R28.2 R30.2 R34.2 R35.2 R36.1 R38.1 R45.1 SIM1.4 U6.5 U6.8 U7.11 U7.25 U7.30 U7.37 U9.C6 U9.E6 U9.F5 U9.J10 U9.K9 U9.M4 U9.N4 U9.P3 U9.P5 U10.C20 U10.D12 U10.E4 U10.F4 U10.G4 U10.G17 U10.M4 U10.T16 | length 3556
  Top Layer w4: R27.2@4698.01,4574.51 R25.2@4698.01,4536.51 R26.2@4698.01,4498.51 R28.2@4698.01,4460.51 4718.99,4460.51 v1(4721,4460.5) ; C59.1@5080,3743.5 5093.29,3730.21 v1(5093.29,3710.59) U7.30@5093.29,3678.6 ; U7.11@5262.56,3509.33 5262.73,3509.5 5332,3509.5 v1(5345,3496.5) C60.1@5366,3496.5 ; U9.P5@6187.24,4187.98 U9.N4@6206.92,4168.29 U9.P3@6226.61,4187.98 ; R36.1@6328,4503.5 R36.1@6328,4506.5 6328,4536.5 6345,4553.5 6409.75,4553.5 ; C7.2@6484.61,4549.11 6487,4546.72 R38.1@6487,4456.5
  Top Layer w5: v1@5237,3869.5 v1(5237,3870.5) ; R7.2@6123.87,4923.4 v4(6123.87,4949.4)
  Top Layer w6: U7.25@5172.03,3678.6 5172.03,3725.53 5185,3738.5 v1(5185,3784.5) ; U10.E4@5634.97,3910.73 5634.97,3936.32 5640,3941.35 5640,3956.89 5634.97,3961.91 v1(5634.97,3981.47) ; C4.2@6369.14,4732.1 R1.2@6410.14,4732.11
  Top Layer w8: v1(4991,3586.5) 5008,3586.5 5037.92,3556.58 U7.37@5065.76,3556.58 ; C30.2@5155,3817.5 5156,3816.5 5179,3816.5 5185,3810.5 v1(5185,3784.5) ; C31.2@5155,3882.5 5156,3881.5 5182,3881.5 5203.95,3859.55 U10.C20@5225.52,3859.55 ; C24.2@5366,3459.5 C60.1@5366,3496.5 ; v1(5635,4073.5) U10.M4@5635,4089.85 ; v3(5741,3821.5) 5763.99,3821.5 C26.2@5764.99,3822.5 ; R34.2@6068,4508.5 6068,4527.5 6075,4534.5 6123,4534.5 6151,4506.5 R36.1@6328,4506.5 ; U9.J10@6088.81,4089.55 U9.K9@6108.5,4109.24 6127.76,4128.5 v1(6128,4128.5) ; v1(6158.02,4030.03) 6167.55,4020.5 U9.E6@6167.55,4010.81 ; U9.C6@6167.55,3971.44 6167.55,3975.24 6149.76,3993.03 U9.E6@6167.55,4010.81 ; U9.F5@6187.24,4030.5 U9.E6@6167.55,4010.81 ; U9.M4@6206.92,4148.61 U9.N4@6206.92,4168.29 ; v1(6227.02,4207.02) 6227.02,4226.52 6247,4246.5 6393.64,4246.5 C69.1@6396.36,4249.22 ; C25.2@6395.99,4118.5 6396.36,4118.87 C73.1@6396.36,4157.85 ; C28.2@6435.95,4083.2 6438.25,4085.5 v1(6494,4085.5) ; C29.2@6436,4047.5 C28.2@6435.95,4083.2
  Top Layer w10: C55.1@4699,4633.51 4717.02,4633.51 v3(4735,4615.5) ; v3(4735,4615.5) U6.5@4761,4589.53 ; U6.8@4911,4589.53 v3(4938.55,4617.08) 4956.96,4635.49 C56.2@4970,4635.49 C27.2@5010,4635.49 ; U10.C20@5225.52,3859.55 5227.05,3859.55 v1@5237,3869.5 ; U10.G17@5302.29,3961.91 v1@5314,3973.62 ; v1(5314,3973.5) v1@5314,3973.62 ; v1@5314.88,3974.5 v1@5314,3973.62 ; v1(5316,4180.5) 5316.15,4180.5 U10.T16@5327.88,4192.23 ; v1(5418,3897.5) 5418,3897.39 U10.D12@5430.24,3885.14 ; U9.P3@6226.61,4187.98 6227.02,4188.4 v1(6227.02,4207.02) ; C4.2@6369.14,4732.1 6369.14,4623.11 v1(6417.14,4575.11) ; C73.1@6396.36,4157.85 C71.1@6396.36,4203.53 C69.1@6396.36,4249.22 ; R1.2@6411.14,4733.11 R1.2@6412.14,4734.11
  Top Layer w12: v1(4523,4504.5) 4523.8,4503.7 LCD1.39@4585.7,4503.7 ; LCD1.5@4585.7,3834.4 4633.9,3834.4 v1(4661,3861.5) ; R27.2@4698.01,4574.51 4698.01,4578.51 v3(4735,4615.5)
  Top Layer w15: v1(6417.14,4546.11) 6419,4544.25 D1.2@6419,4462.7
  Mid-Layer 1 w10: v1(5418,3897.5) 5457,3897.5 5516,3956.5 5601,3956.5 5610,3965.5 5619,3965.5 v1(5634.97,3981.47)
  Mid-Layer 2 w8: v1(5634.97,3981.47) 5644,3972.44 5644,3919.5 5667,3896.5 5698,3896.5 5738,3856.5 5738,3824.5 v3(5741,3821.5)
  Mid-Layer 2 w10: v1(5314,3973.5) 5314,3929.5 5346,3897.5 v1(5418,3897.5) ; v1(5316,4180.5) 5316,4147.5 5339,4124.5 5339,4103.5 v1(5366,4076.5)
  other v1: 4412,3391.5 5415,3623.5 5491,3624.5 6888,4159.5 6442.14,4546.11 6442.14,4575.07
  other v3: 6512,3675.74
$1N3408: C4.1 R1.1 R2.2 U1.5 | length 162.3
  Top Layer w6: C4.1@6369.14,4772.1 6410.14,4772.11 R1.1@6412.14,4770.11
  Top Layer w10: R1.1@6412.14,4770.11 R2.2@6412.14,4815.11 6415.14,4818.11 6441.14,4818.11 6464.32,4841.29 U1.5@6474.74,4841.29
$1N3418: C10.1 R3.1 R4.2 U2.5 | length 180.1
  Top Layer w10: R3.1@5906.87,4768.4 5872.87,4768.4 C10.1@5869.87,4771.39 5869.87,4799.4 5881.87,4811.4 R4.2@5906.87,4811.4 5910.87,4815.4 5930.87,4815.4 5959.05,4843.58 U2.5@5965.47,4843.58
$1N3424: C14.1 R5.1 R6.2 U3.5 | length 154.1
  Top Layer w10: C14.1@6122.87,4768.39 R5.1@6159.87,4768.4 ; R5.1@6161.87,4766.4 R5.1@6159.87,4768.4 ; U3.5@6220.87,4840.4 6216.87,4840.4 6188.87,4812.4 6163.87,4812.4 R6.2@6161.87,4810.4 6161.87,4770.4 R5.1@6159.87,4768.4
$1N3432: L1.1 U1.3 | length 99
  Top Layer w20: L1.1@6546.74,4641.11 6549.54,4643.91 U1.3@6549.54,4738.92
$1N3433: L2.1 U2.3 | length 100.4
  Top Layer w20: L2.1@6036.47,4642.4 6040.27,4646.2 U2.3@6040.27,4741.21
$1N3434: L3.1 U3.3 | length 103.4
  Top Layer w20: L3.1@6286.87,4638.4 6286.87,4683.4 6295.87,4692.4 6295.87,4737.83 U3.3@6295.67,4738.03
$1N14012: D1.1 U10.M7 | length 995.4
  Top Layer w10: U10.M7@5559.7,4090.02 5572,4102.32 v3(5572,4102.5)
  Top Layer w15: v6(6419,4346.5) D1.1@6419,4376.3
  Bottom Layer w15: v3(5572,4102.5) 5646,4102.5 5856,4312.5 6385,4312.5 v6(6419,4346.5)
$1N24003: C2.2 U10.B19 | length 153.6
  Top Layer w6: U10.B19@5251.11,3833.96 5264,3821.08 5264,3765.5 5276,3753.5 5302,3753.5 5316,3739.5 C2.2@5316,3722.51
$1N24126: C3.2 U10.B18 | length 161.4
  Top Layer w6: U10.B18@5276.7,3833.96 5290,3820.67 5290,3798.5 5301,3787.5 5333,3787.5 5352,3768.5 C3.2@5352,3722.51
$2N3534: R12.2 U10.U17 | length 281.8
  Top Layer w4: R12.2@5142,4299.2 5156.7,4284.5 v1(5158,4284.5) ; v1(5289.7,4205.26) 5289.7,4206.26 5301.27,4217.82 U10.U17@5302.29,4217.82
  Mid-Layer 1 w8: v1(5158,4284.5) 5186,4256.5 5239,4256.5 5256,4273.5 5298,4273.5 5307,4264.5 5307,4216.5 5295.76,4205.26 v1(5289.7,4205.26)
$2N3599: R9.1 U4.L9 | length 126.8
  Top Layer w4: U4.L9@5388.5,4553.65 5388.5,4491.15 5419.5,4460.15 5419.5,4441.15 R9.1@5420.5,4440.15
$2N3600: R10.1 U4.L8 | length 154.3
  Top Layer w4: R10.1@5376.5,4439.15 5372.5,4443.15 5372.5,4569.15 U4.L8@5388.5,4585.15
$3N2270: R19.1 USB2.B5 | length 64.8
  Top Layer w10: R19.1@6610,4713.5 6610.67,4712.82 USB2.B5@6674.55,4712.82
$3N2271: R16.2 USB2.A5 | length 64.5
  Top Layer w10: R16.2@6611,4592.5 6613.21,4594.71 USB2.A5@6674.57,4594.71
$3N4631: LCD1.11 R29.2 | length 108.6
  Top Layer w4: LCD1.11@4585.7,3952.5 4683,3952.5 R29.2@4691,3960.5
$3N5659: R18.1 USB1.B5 | length 62.2
  Top Layer w8: R18.1@3732,4689.5 3732,4751.11 USB1.B5@3732.41,4751.52
$3N5660: R15.2 USB1.A5 | length 62.2
  Top Layer w8: USB1.A5@3850.52,4751.54 3851,4751.06 R15.2@3851,4689.5
$3N7064: R20.1 USB3.B5 | length 64.4
  Top Layer w10: R20.1@6620,3752.5 6624.1,3748.4 USB3.B5@6682.71,3748.4
$3N7065: R17.2 USB3.A5 | length 63.3
  Top Layer w10: R17.2@6621,3626.5 6624.78,3630.29 USB3.A5@6682.73,3630.29
$3N9738: D2.2 L4.2 U5.1 | length 177.9
  Top Layer w18: D2.2@4205.2,4703.5 4255.4,4703.5 L4.2@4278.4,4726.5 4271,4733.9 4271,4750.5 4248.4,4773.1 U5.1@4212.24,4773.1
$3N13237: R23.2 U6.6 | length 221.7
  Top Layer w4: U6.6@4811,4589.53 4827,4573.53 4827,4540.5 4854,4513.5 4926,4513.5 4953.5,4541 R23.2@4970.5,4541
$3N13261: R24.2 U6.7 | length 219.6
  Top Layer w4: U6.7@4861,4589.53 4846,4574.53 4846,4542.5 4862,4526.5 4920,4526.5 4947,4553.5 4947,4571.5 4961.5,4586 R24.2@4970.5,4586
$6N792: R37.1 U10.B2 | length 112.6
  Top Layer w4: U10.B2@5686.15,3833.96 5698.61,3821.5 5698.61,3784.88 5713,3770.5 R37.1@5713,3732.5
$6N4195: C57.2 R31.1 U7.40 | length 75.7
  Top Layer w8: C57.2@5025.16,3509.2 5025.29,3509.33 U7.40@5065.76,3509.33
  Top Layer w20: R31.1@4990.15,3509.19 C57.2@5025.16,3509.2
$6N4196: C58.2 R31.2 U8.1 | length 241
  Top Layer w20: U8.1@4784.15,3382.73 cw(c4912.16,3380.16) 4912.16,3508.2 4953.16,3508.2 R31.2@4954.15,3509.19
$6N4201: C64.1 U7.26 | length 65.4
  Top Layer w4: C64.1@5155,3743.51 5155,3679.88 U7.26@5156.29,3678.6
$6N4202: C63.1 U7.21 | length 44.9
  Top Layer w4: U7.21@5235.03,3678.6 C63.1@5235,3723.5
$6N4203: C62.1 U7.2 | length 104.7
  Top Layer w4: C62.1@5066.99,3394.5 5067,3412.5 5109.04,3454.54 U7.2@5109.04,3481.8
$6N4204: C61.1 U7.38 | length 79.7
  Top Layer w8: C61.1@4991.16,3553.2 4993.16,3551.2 5021.16,3551.2 5031.53,3540.83 U7.38@5065.76,3540.83
$6N4213: C65.1 C66.1 C67.1 U7.1 U7.22 U7.28 U7.36 | length 1025.4
  Top Layer w4: C67.1@4989,3434.49 v1(5044.38,3434.5) 5074,3434.5 5093,3453.5 5093,3481.51 U7.1@5093.29,3481.8 ; C65.1@4989.99,3618.5 4997,3618.5 5043.17,3572.33 U7.36@5065.76,3572.33 ; C66.1@5118,3743.5 5124.79,3736.71 v1(5124.79,3713) U7.28@5124.79,3678.6 ; U7.22@5219.28,3678.6 5219.28,3703.22 5212,3710.5 5212,3738.5 5225,3751.5 v1(5234,3751.5)
  Bottom Layer w15: v1(5044.38,3434.5) 5069,3434.5 5087,3452.5 5087,3583.5 5057,3613.5 v1(5001,3613.5) 5001,3616.5 4990,3627.5 4990,3679.5 5004,3693.5 5033,3693.5 5043,3683.5 5095.29,3683.5 v1(5124.79,3713) 5130.29,3718.5 5149,3718.5 5182,3751.5 v1(5234,3751.5)
$6N12118: R32.1 U8.2 | length 89.7
  Top Layer w10: R32.1@4573,3381.5 4660.93,3381.5 U8.2@4662.15,3382.73
$7N781: C68.2 C70.2 C72.2 U9.C2 | length 285
  Top Layer w3.5: 6285.02,3970.03 6276.02,3961.03 6256.7,3961.03 U9.C2@6246.29,3971.44 6255.87,3981.03 6276.02,3981.03 6287.02,3970.03
  Top Layer w8: 6287.02,3970.03 6289.5,3972.5 C70.2@6395.99,3972.5 ; C68.2@6395.99,3934.5 C70.2@6395.99,3972.5 ; C72.2@6395.99,4011.5 C70.2@6395.99,3972.5
  Top Layer w10: 6285.02,3970.03 6287.02,3970.03
$7N6008: R46.1 U10.G3 | length 111.2
  Top Layer w4: U10.G3@5660.56,3961.91 5672.98,3949.5 5761,3949.5 R46.1@5765,3945.5
$7N7080: R47.1 U10.D2 | length 85.9
  Top Layer w4: U10.D2@5686.15,3885.14 5697.8,3873.5 5763,3873.5 R47.1@5766,3876.5
$7N18220: CN1.16 R41.1 R43.2 | length 766.3
  Top Layer w5: R41.1@3755,3748.5 3755,3734.5 3780.5,3709 CN1.16@3780.5,3592.7 3780.5,3512 3846,3446.5 4233,3446.5 R43.2@4261,3418.5
$7N18268: CN1.15 R40.1 R42.2 | length 719.1
  Top Layer w5: R40.1@3796,3747.5 3796,3592 3796.3,3591.7 3796,3591.4 3796,3517.5 3853,3460.5 4257,3460.5 R42.2@4260,3457.5
$7N19855: CN1.18 D5.1 R42.1 R43.1 | length 1079.5
  Top Layer w5: v1(4296,3392.5) R43.1@4296,3418.5 R42.1@4296,3457.5
  Top Layer w8: D5.1@3659,3718.3 3659,3664.5 v1(3696,3627.5) 3709,3614.5 3709,3567.5 3722,3554.5 3741,3554.5 3749,3562.5 CN1.18@3749,3592.7 ; 4277.34,3411.16 v1(4296,3392.5)
  Mid-Layer 1 w6: v1(3696,3627.5) 3714,3609.5 3742,3609.5 3780,3571.5 3780,3502.5 3853,3429.5 4157,3429.5 4194,3392.5 v1(4296,3392.5)
$7N20557: CN1.13 D6.1 R39.1 | length 684.5
  Top Layer w5: CN1.13@3827.8,3591.7 3827,3590.9 3827,3510.5 3864,3473.5 4232,3473.5 4241,3482.5 4320.8,3482.5 D6.1@4343.8,3459.5
  Top Layer w10: R39.1@4340,3403.5 4340,3455.7 D6.1@4343.8,3459.5
$7N21242: D6.2 R45.2 | length 78.2
  Top Layer w18: D6.2@4430.2,3459.5 4448,3459.5 4461,3446.5 R45.2@4461,3404.5
$7N21477: CN1.19 R44.1 | length 165.2
  Top Layer w5: R44.1@3713,3748.5 3713,3693.5 3733.3,3673.2 CN1.19@3733.3,3591.7
AP_CLK_OUT: R33.1 U7.3 U10.J2 | length 1081.9
  Top Layer w6: U7.3@5124.79,3481.8 5124.79,3437.71 5134,3428.5 v1(5141,3428.5) ; U10.J2@5686.15,4013.09 5709.59,4013.09 v1(5710,4013.5)
  Mid-Layer 1 w8: v1(5141,3428.5) 5142,3427.5 5215,3427.5 5261,3473.5 5261,3783.5 5482,4004.5 5701,4004.5 v1(5710,4013.5)
AP_WAKE_BT: U7.5 U10.D5 | length 1043.6
  Top Layer w4: U7.5@5156.29,3481.8 5156.29,3451.21 5239,3368.5 5555,3368.5 5629,3442.5 5629,3472.5 5646,3489.5 5646,3573.5 5630,3589.5 v1(5630,3591.5) ; v1@5597,3872.5 v1(5597,3872.76) U10.D5@5609.38,3885.14
  Mid-Layer 2 w4: v1(5597,3872.76) 5622,3847.76 5622,3599.5 v1(5630,3591.5)
AVCC: C1.2 U10.C18 U10.C19 | length 127.9
  Top Layer w6: C1.2@5155,3848.5 5157,3846.5 5238.06,3846.5 5251.11,3859.55 U10.C18@5276.7,3859.55
BT_RSTN: U7.23 U10.D6 | length 632.8
  Top Layer w4: U7.23@5203.53,3678.6 5203.53,3745.03 5219,3760.5 v1(5219,3778.5) ; v1(5535,3898.5) 5570.44,3898.5 U10.D6@5583.79,3885.14
  Bottom Layer w4: v1(5219,3778.5) 5239,3778.5 5274,3743.5 5485,3743.5 5506,3764.5 5506,3858.5 5535,3887.5 v1(5535,3898.5) 5551,3898.5
BT_WAKE_AP: U7.6 U10.E6 | length 1048.7
  Top Layer w4: U7.6@5172.03,3481.8 5172.03,3450.47 5243,3379.5 5552,3379.5 5619,3446.5 5619,3478.5 5636,3495.5 5636,3547.5 v1(5622,3561.5) ; U10.E6@5583.79,3910.73 v1(5596,3898.53)
  Mid-Layer 2 w4: v1(5596,3898.53) 5591.02,3898.53 5575,3882.5 5575,3839.5 5611,3803.5 5611,3572.5 v1(5622,3561.5)
CTP_INT: LCD1.35 R28.1 U10.G16 | length 1975.9
  Top Layer w4: v1(4367,4430.5) 4384,4413.5 4483,4413.5 4494.4,4424.9 4614.4,4424.9 4650.01,4460.51 R28.1@4662.01,4460.51
  Top Layer w6: U10.G16@5327.88,3961.91 5340,3949.8 v1(5340,3949.5)
  Bottom Layer w6: v1(4367,4430.5) 4388,4409.5 4388,3890.5 4486,3792.5 4776,3792.5 4963,3979.5 5226,3979.5 5248,3957.5 5274,3957.5 5281,3964.5 5299,3964.5 5314,3949.5 v1(5340,3949.5)
CTP_RST: LCD1.38 R27.1 U10.G15 | length 1972.3
  Top Layer w4: v1(4472,4492.5) 4480.5,4484 LCD1.38@4585.7,4484 4618.5,4484 4623,4488.5 4623,4515.5 4642,4534.5 4642,4554.5 R27.1@4662.01,4574.51
  Top Layer w6: v1(5341,3977.5) 5353.47,3965.03 U10.G15@5353.47,3961.91
  Bottom Layer w6: v1(4472,4492.5) 4471,4493.5 4461,4493.5 4403,4435.5 4403,3896.5 4494,3805.5 4770,3805.5 4957,3992.5 5328,3992.5 5341,3979.5 v1(5341,3977.5)
CTP_SCK: LCD1.37 R25.1 U10.J16 | length 1890.3
  Top Layer w4: v1(4472,4466.5) 4474.2,4464.3 LCD1.37@4585.7,4464.3 4617.8,4464.3 4632,4478.5 4632,4506.5 R25.1@4662.01,4536.51
  Top Layer w6: U10.J16@5327.88,4013.09 5340,4025.21 v1(5340,4025.5)
  Bottom Layer w6: v1(4472,4466.5) 4460,4466.5 4418,4424.5 4418,3901.5 4500,3819.5 4765,3819.5 4951,4005.5 5320,4005.5 v1(5340,4025.5)
CTP_SDA: LCD1.36 R26.1 U10.J17 | length 1792.3
  Top Layer w4: v1(4472,4441.5) 4475.1,4444.6 LCD1.36@4585.7,4444.6 4616.1,4444.6 4641,4469.5 4641,4491.5 4648.01,4498.51 R26.1@4662.01,4498.51
  Top Layer w6: U10.J17@5302.29,4013.09 5313.7,4024.5 v1(5314,4024.5)
  Bottom Layer w6: v1(4472,4441.5) 4459,4441.5 4432,4414.5 4432,3908.5 4507,3833.5 4760,3833.5 4945,4018.5 5308,4018.5 v1(5314,4024.5)
D0+: U10.B7 USB2.A6 USB2.B6 | length 2221.1
  Top Layer w4: v1(6603,4659.5) 6621,4659.5 6634.95,4673.45 USB2.B6@6674.55,4673.45 6707.37,4673.45 6714.84,4665.98 6714.84,4641.92 6707,4634.08 USB2.A6@6674.55,4634.08
  Top Layer w5: v1@5547,3845.5 v1(5547,3845.17) U10.B7@5558.2,3833.96
  Mid-Layer 1 w4: v1(5547,3845.17) 5547,3834.5 5567,3814.5 5698,3814.5 5723,3839.5 5818,3839.5 5834,3823.5 5834,3771.5 v3(5824,3761.5)
  Bottom Layer w4: v3(5824,3761.5) 5834,3771.5 5834,3786.5 5866,3818.5 6521,3818.5 6615,3912.5 6615,4588.5 6587,4616.5 6587,4643.5 v1(6603,4659.5)
D0-: U10.C7 USB2.A7 USB2.B7 | length 2175.8
  Top Layer w4: v1(6603,4633.5) 6620.42,4633.5 6632.84,4645.92 ; USB2.B7@6674.55,4614.39 6641.37,4614.39 6632.84,4622.92 6632.84,4645.92 ; USB2.A7@6674.55,4653.76 6641,4653.76 6640.84,4653.92 6632.84,4645.92
  Top Layer w5: v1@5545,3872.5 v1(5545.26,3872.5) U10.C7@5558.2,3859.55
  Mid-Layer 1 w4: v1(5545.26,3872.5) 5563,3854.76 5563,3834.5 5573,3824.5 5693,3824.5 5718,3849.5 5822,3849.5 5844,3827.5 5844,3771.5 v3(5853,3762.5)
  Bottom Layer w4: v3(5853,3762.5) 5844,3771.5 5844,3784.5 5869,3809.5 6524,3809.5 6624,3909.5 6624,4593.5 6603,4614.5 v1(6603,4633.5)
D1+: U10.A8 USB3.A6 USB3.B6 | length 1354.5
  Top Layer w4: v3(5764,3777.5) 5783,3796.5 5869,3796.5 5884,3781.5 6557,3781.5 6583,3755.5 6583,3724.5 6633,3674.5
  Top Layer w5: v1(5521,3818.5) 5521.51,3818.5 5522,3818.99 U10.A8@5532.61,3808.37
  Top Layer w6: USB3.A6@6682.71,3669.66 6637.84,3669.66 6633,3674.5 6633,3703.5 6638.53,3709.03 USB3.B6@6682.71,3709.03
  Mid-Layer 1 w4: v1(5521,3818.5) 5544,3795.5 5746,3795.5 v3(5764,3777.5)
D1-: U10.B8 USB3.A7 USB3.B7 | length 1409.5
  Top Layer w4: v3(5792,3777.5) 5802,3787.5 5865,3787.5 5880,3772.5 6552,3772.5 6574,3750.5 6574,3719.5 6643.53,3649.97 USB3.B7@6682.71,3649.97
  Top Layer w5: v1(5521.07,3845.5) U10.B8@5532.61,3833.96
  Top Layer w6: USB3.B7@6682.71,3649.97 6719.47,3649.97 6729,3659.5 6729,3679.5 6719.16,3689.34 USB3.A7@6682.71,3689.34
  Mid-Layer 1 w4: v1(5521.07,3845.5) 5536,3830.58 5536,3824.5 5557,3803.5 5764,3803.5 5790,3777.5 v3(5792,3777.5)
DU+: U6.1 USB1.A6 USB1.B6 | length 1480
  Top Layer w4: USB1.A6@3811.15,4751.52 3811.15,4714.65 3805,4708.5 3777,4708.5 3772,4713.5 3772,4751.3 3771.78,4751.52 3771.78,4788.28 3779,4795.5 3779,4844.81 3823.69,4889.5 4015.69,4889.5 4064.69,4938.5 4848,4938.5 4890,4896.5 4890,4876.54 4911,4855.54 U6.1@4911,4807.47
DU-: U6.2 USB1.A7 USB1.B7 | length 1411.5
  Top Layer w4: USB1.A7@3791.47,4751.52 3791.47,4783.87 ; USB1.B7@3830.84,4751.52 3832,4752.68 3832,4783.5 3824,4791.5 3799.1,4791.5 3791.47,4783.87 ; U6.2@4861,4807.47 4861,4855.54 4882,4876.54 4882,4890.5 4842,4930.5 4068,4930.5 4019,4881.5 3827,4881.5 3787,4841.5 3787,4805.5 3791.47,4801.03 3791.47,4783.87
EMMC_CLK: R46.2 U9.M6 | length 574
  Top Layer w4: R46.2@5801,3945.5 5850,3945.5 v1(5857,3938.5) ; v1(6158.02,4129.02) 6167.55,4138.55 U9.M6@6167.55,4148.61
  Bottom Layer w4: v1(5857,3938.5) 5857,3944.51 5868.99,3956.5 6129,3956.5 6174,4001.5 6174,4042.5 6145,4071.5 6145,4103.5 6158.02,4116.52 v1(6158.02,4129.02)
EMMC_CMD: U9.M5 U10.G2 | length 733
  Top Layer w4: U10.G2@5686.15,3961.91 5739.41,3961.91 5742,3964.5 5862,3964.5 v1(5888,3938.5) ; U9.M5@6187.24,4148.61 6187.24,4138.81 v1@6196.52,4129.52 ; v1@6196.52,4129.52 6197.02,4128.02 6198.02,4128.02 v1@6196.52,4129.52
  Bottom Layer w4: v1(5888,3938.5) 5898,3948.5 6136,3948.5 6184,3996.5 6184,4046.5 6152.67,4077.83 6152.67,4098.17 6163,4108.5 6177,4108.5 6196.02,4127.52 v1(6196.02,4129.02)
EMMC_D0: U9.A3 U10.G6 | length 789.2
  Top Layer w4: U10.G6@5583.79,3961.91 5583.79,3982.29 v1(5584,3982.5) ; v1(5928,3881.5) 5931,3884.5 5931,3886.5 5947,3902.5 5969,3902.5 6001,3870.5 6179,3870.5 6226.61,3918.11 U9.A3@6226.61,3932.07
  Bottom Layer w4: v1(5584,3982.5) 5593,3973.5 5593,3935.5 5639,3889.5 5704,3889.5 5706,3887.5 5741,3887.5 5747,3893.5 5916,3893.5 v1(5928,3881.5)
EMMC_D1: U9.A4 U10.F5 | length 679.2
  Top Layer w4: U10.F5@5609.38,3936.32 v1(5621,3947.94) v1@5621,3948.5 ; v1(5938,3918.5) 5943,3923.5 5962,3923.5 6006,3879.5 6175,3879.5 6206.92,3911.42 U9.A4@6206.92,3932.07
  Bottom Layer w4: v1(5621,3947.94) 5660.44,3908.5 5713,3908.5 5715,3906.5 5732,3906.5 5737,3911.5 5902,3911.5 5909,3918.5 v1(5938,3918.5)
EMMC_D2: U9.A5 U10.H3 | length 600.6
  Top Layer w4: U10.H3@5660.56,3987.5 5673.56,3974.5 5926,3974.5 6011.35,3889.15 6170.65,3889.15 6187.24,3905.74 U9.A5@6187.24,3932.07
EMMC_D3: U9.B2 U10.G5 | length 802.3
  Top Layer w3.5: 6236,3919.5 6236,3941.47 U9.B2@6246.29,3951.76
  Top Layer w4: v1@5609,3983.5 v1(5609.38,3983.12) U10.G5@5609.38,3961.91 ; v1(5959,3885.5) 5983,3861.5 6184,3861.5 6236,3913.5 6236,3919.5
  Bottom Layer w4: v1(5609.38,3983.12) 5603,3976.74 5603,3939.5 5643,3899.5 5709,3899.5 5712,3896.5 5735,3896.5 5741,3902.5 5942,3902.5 v1(5959,3885.5)
EMMC_RST: U9.K5 U10.F1 | length 652.3
  Top Layer w4: U10.F1@5711.74,3936.32 v1(5725.56,3922.5) v1@5726,3922.5 ; v1(6167.02,4089.03) U9.K5@6187.24,4109.24
  Bottom Layer w4: v1(5725.56,3922.5) 5900,3922.5 5916,3938.5 6139,3938.5 6193,3992.5 6193,4054.5 6167.02,4080.48 v1(6167.02,4089.03)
